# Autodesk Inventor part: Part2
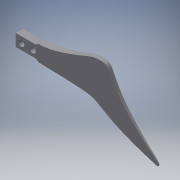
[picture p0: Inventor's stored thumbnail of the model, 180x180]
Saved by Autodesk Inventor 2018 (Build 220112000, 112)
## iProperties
Created: 2019-06
Part Number: Part2
Material: Generic
Document SubType Name: Modeling
Designer: multivac
Density: 1 g/cm^3
Appearance: Default
Author: multivac
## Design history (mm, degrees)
sketch "Sketch1"
  geometry: L1 (-3.819, -19.846)-(189.926, -19.846); L2 (189.926, -19.846)-(189.926, -98.849); L3 (189.926, -98.849)-(-3.819, -98.849); L4 (-3.819, -98.849)-(-3.819, -19.846); L5 (137.738, -41.582)-(144.486, -41.582); L6 (144.486, -41.582)-(155.141, -38.487); L7 (155.141, -38.487)-(163.817, -35.443); L8 (163.817, -35.443)-(171.428, -32.196); L9 (171.428, -32.196)-(174.067, -31.587); L10 (174.067, -31.587)-(180.257, -31.587); L11 (180.257, -31.587)-(182.286, -33.16); L12 (182.286, -33.16)-(186.396, -42.699); L13 (186.396, -42.699)-(193.601, -52.542); L14 (193.601, -52.542)-(207.808, -67.104); L15 (207.808, -67.104)-(215.908, -72.663); L16 (215.908, -72.663)-(214.693, -75.276); L17 (214.693, -75.276)-(212.527, -73.903); L18 (212.527, -73.903)-(203.749, -71.214); L19 (203.749, -71.214)-(189.745, -65.379); L20 (189.745, -65.379)-(181.068, -60.559); L21 (181.068, -60.559)-(173.305, -55.282); L22 (173.305, -55.282)-(170.261, -54.064); L23 (170.261, -54.064)-(151.944, -52.897); L24 (151.944, -52.897)-(137.332, -52.085); L25 (137.332, -52.085)-(137.332, -41.582); L26 (137.332, -41.582)-(137.738, -41.582); 1 further point; 1 other entity
  constraints: 4 end point, 2 horizontal, 1 collinear, 1 vertical, 5 other
extrude "Extrusion1" new body sketch "Sketch1" distance "d15" = 5; taper "d16" = 0 deg
sketch "Sketch3"
  geometry: L1 (-137.738, 5)-(-137.332, 5) reference; L2 (-137.332, 0)-(-137.332, 5) reference; L3 (-137.332, 5)-(-137.332, 0); L4 (-224.527, 2.5)-(-137.332, 5); L5 (-137.332, 0)-(-137.738, 0) reference; L6 (-137.332, 0)-(-224.527, 2.5); 1 further point
  constraints: 6 end point, 1 vertical
extrude "Extrusion2" sketch "Sketch3" distance "d20" = 100; taper "d21" = 0 deg
sketch "Sketch4"
  geometry: L1 (0, 5.251)-(0, 9.251); L2 (0, 9.251)-(5, 9.251); L3 (0, 5.251)-(0, 1.251); L4 (0, 1.251)-(5, 1.251); L5 (5, 9.251)-(5, 1.251); 1 further point
  constraints: 10 end point, 1 perpendicular
  dimensions: "d30" = 4 distance of L1.start L1.end; "d31" = 4 distance of L1.start L3.end
extrude "Extrusion3" join sketch "Sketch4" distance "d27" = 15; taper "d28" = 0 deg
fillet "Fillet2" dims "d32" = 3
sketch "Sketch5"
  geometry: C1 r 2 at (11.25, 4); C2 r 2 at (3.75, 4); 1 further point
  constraints: 2 centre point
  dimensions: "d36" = 4 diameter of C1; "d37" = 4 diameter of C2
extrude "Extrusion4" cut sketch "Sketch5" distance "d38" = 5; taper "d39" = 0 deg
body "Solid1"
node "Image1"
